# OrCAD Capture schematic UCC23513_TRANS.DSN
size Custom; title: UCC23513 3-A, 5-kVRMS Opto-Compatible Single; rev: 1.0; note: Datasheet: SLUSD31     EVM: SLUUBW3; note: Synchronous Step Down Converter
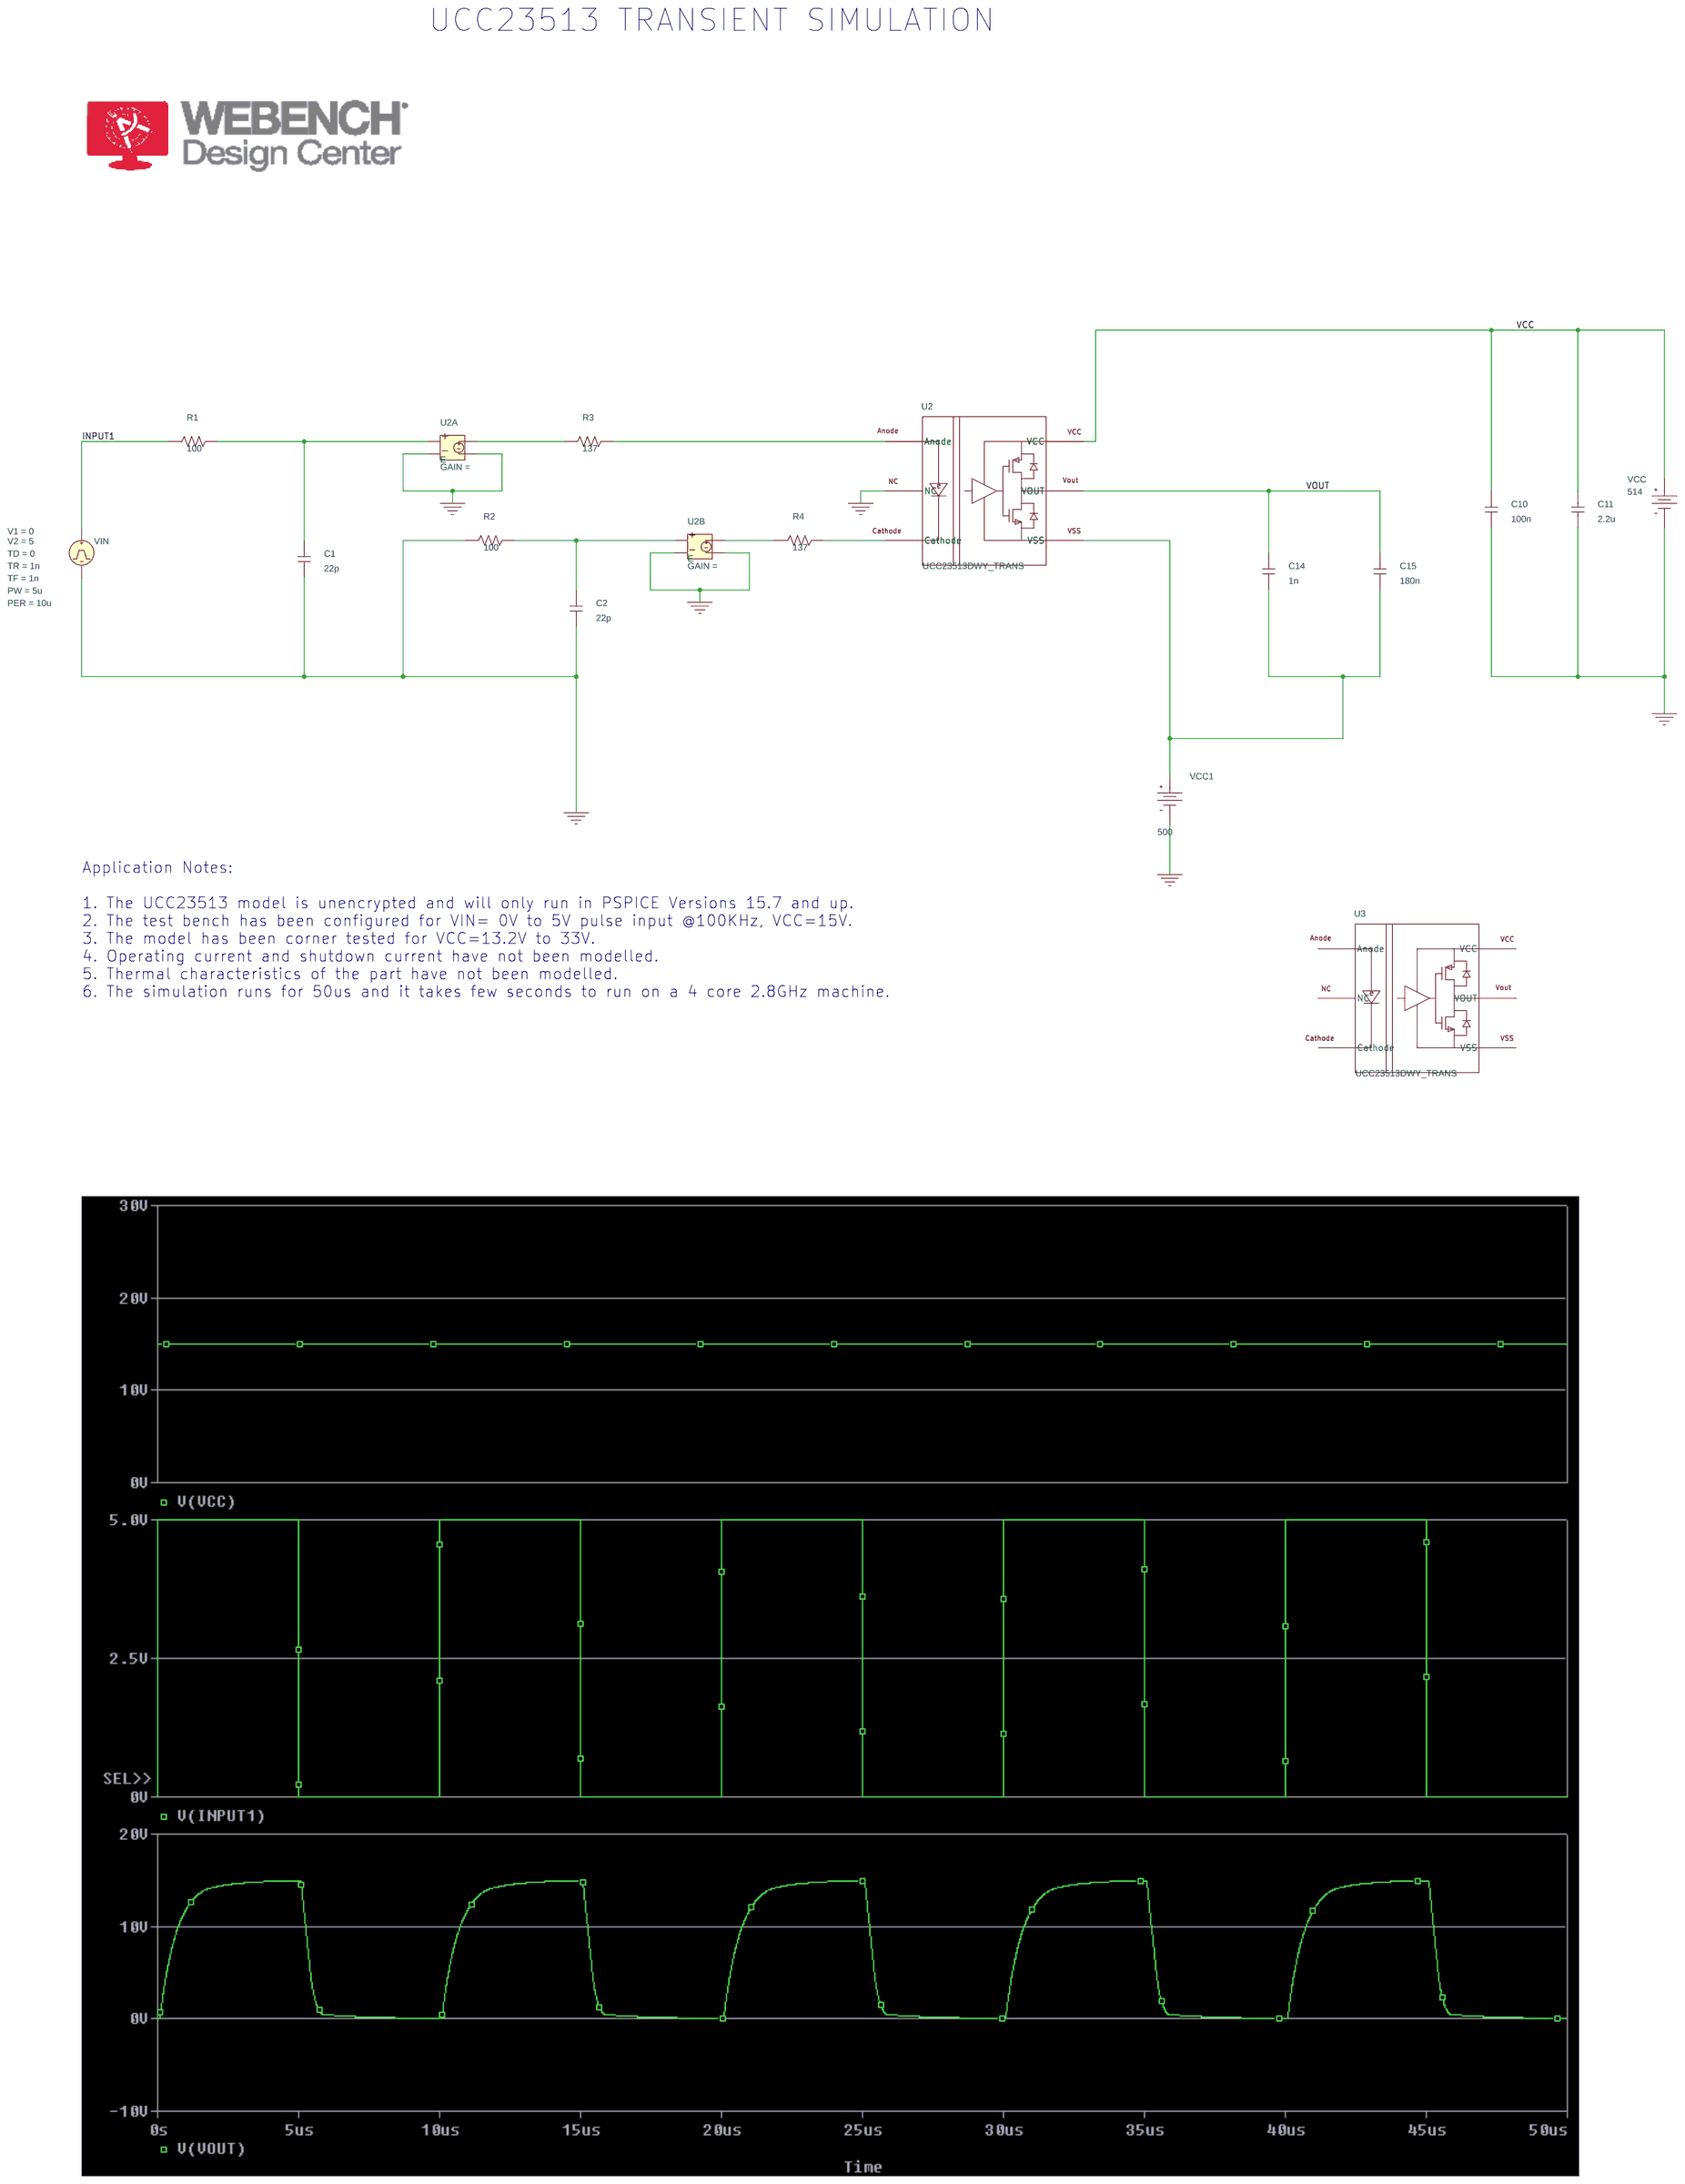
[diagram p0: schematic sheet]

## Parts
C1  22p  [RAD/CK05]
C2  22p  [RAD/CK05]
C10  100n  [RAD/CK05]
C11  2.2u  [RAD/CK05]
C14  1n  [RAD/CK05]
C15  180n  [RAD/CK05]
R1  100  [AX/RC05]
R2  100  [AX/RC05]
R3  137  [AX/RC05]
R4  137  [AX/RC05]
U2  UCC23513DWY_TRANS  [DWY0006A]
U2A  E
U2B  E
U3  UCC23513DWY_TRANS  [DWY0006A]
VCC  VDC
VCC1  VDC
VIN  VPULSE

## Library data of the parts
C1 C2 C10 C11 C14 C15 = C
R1-R4 = R
U2 U3 = UCC23513DWY_TRANS
U2A U2B = E
VCC = VDC: DC: 514
VCC1 = VDC: DC: 500
VIN = VPULSE: PER: 10u; PW: 5u; TD: 0; TF: 1n; TR: 1n; V1: 0; V2: 5

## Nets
VCC: C10.1 C11.1 U2.6(VCC) U3.6(VCC) VCC.0(+)
VSS: U3.4(VSS)
0: C1.2 C2.2 C10.2 C11.2 R2.1 U2.2(NC) U2A.2 U2A.4 U2B.2 U2B.4 VCC.1(-) VCC1.1(-) VIN.2(-)
INPUT1: R1.1 VIN.1(+)
VOUT: C14.1 C15.1 U2.5(VOUT) U3.5(VOUT)
N00172: C1.1 R1.2 U2A.1
N00418: C2.1 R2.2 U2B.1
N00620: R3.1 U2A.3
N00644: R3.2 U2.1(Anode)
N00943: R4.1 U2B.3
N00975: R4.2 U2.3(Cathode)
N01472: C14.2 C15.2 U2.4(VSS) VCC1.0(+)

Not connected (* = marked no-connect by the designer): U3 1(Anode) 2(NC) 3(Cathode)

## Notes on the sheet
- UCC23513 TRANSIENT SIMULATION
- Application Notes:
  1. The UCC23513 model is unencrypted and will only run in PSPICE Versions 15.7 and up.
  2. The test bench has been configured for VIN= 0V to 5V pulse input @100KHz, VCC=15V.
  3. The model has been corner tested for VCC=13.2V to 33V.
  4. Operating current and shutdown current have not been modelled.
  5. Thermal characteristics of the part have not been modelled.
  6. The simulation runs for 50us and it takes few seconds to run on a 4 core 2.8GHz machine.
